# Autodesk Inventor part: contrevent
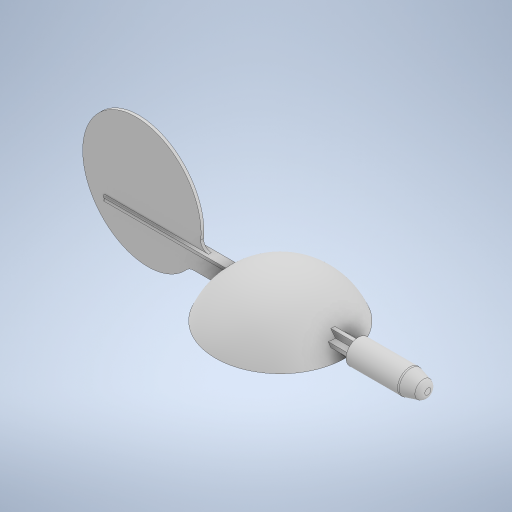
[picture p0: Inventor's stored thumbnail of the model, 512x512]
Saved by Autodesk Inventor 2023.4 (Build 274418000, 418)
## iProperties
Created: 2024-03
Part Number: contrevent
Material: Générique
Document SubType Name: Modeling
Designer: mel
Density: 1 g/cm^3
Appearance: Par défaut
Author: mel
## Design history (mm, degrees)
sketch "Esquisse1"
  geometry: L1 (0, 35.875)-(0, -35.875); A1 r 35.875 centre (0, 0) between (0, -35.875) and (0, 35.875); 1 further point
  constraints: 2 end point, 2 point on circle, 1 centre point, 1 coincident, 1 vertical
  dimensions: "d0" = 71.75 diameter of A1
revolve "Révolution1" sketch "Esquisse1" stored, may be unused: angle "d1" = 90 deg
node "Plan de construction1"
sketch "Esquisse3"
  geometry: C1 r 35.875 at (0, 0) reference; 1 further point
extrude "Extrusion1" cut sketch "Esquisse3" extent not by distance; stored distance "d3" = 0; taper "d4" = 0 deg
feature "Coque1" dims "d5" = 1.35
sketch "Esquisse4"
  geometry: C1 r 1.75 at (29.595, -0.936); C2 r 33.485 at (0, 0) reference; A1 r 2.625 centre (29.595, -0.936) between (32.034, 0.034) and (31.968, -2.058); A2 r 32.035 centre (0, 0) between (31.968, -2.058) and (32.034, 0.034) reference; 1 further point
  constraints: 4 point on circle, 2 centre point, 1 coincident
  dimensions: "d6" = 3.5 diameter of C1; "d7" = 5.25 diameter of A1; "d8" = 6.5 dimension on C2 A1
extrude "Extrusion2" join sketch "Esquisse4" stored distance "d9" = 10; taper "d10" = 0 deg
sketch "Esquisse5"
  geometry: C1 r 5 at (0, 0); C2 r 6 at (0, 0); 1 further point
  constraints: 2 centre point, 2 coincident
  dimensions: "d11" = 10 diameter of C1; "d12" = 12 diameter of C2
extrude "Extrusion3" join sketch "Esquisse5" stored distance "d13" = 10; taper "d14" = 0 deg
sketch "Esquisse6"
  geometry: C1 r 6 at (0, 0) reference; C2 r 5 at (0, 0) reference; 1 further point
extrude "Extrusion4" cut sketch "Esquisse6" distance "d15" = 3; taper "d16" = 0 deg
sketch "Esquisse7"
  geometry: L1 (0, 0)-(26.039, -26.039); L2 (0, 0)-(35.773, 0) reference; L3 (3.947, -3.947)-(16.753, -16.753); L4 (16.753, -16.753)-(16.399, -17.106); L5 (16.399, -17.106)-(3.593, -4.3); L6 (3.593, -4.3)-(3.947, -3.947); L7 (3.947, -3.947)-(16.753, -16.753); L8 (16.753, -16.753)-(17.106, -16.399); L9 (17.106, -16.399)-(4.3, -3.593); L10 (4.3, -3.593)-(3.947, -3.947); C1 r 6 at (0, 0) reference; A1 r 32.035 centre (0, 0) between (32.034, 0.034) and (31.968, -2.058) reference; 2 further points
  constraints: 20 end point, 5 parallel, 2 horizontal, 2 perpendicular, 2 point on line, 1 other
  dimensions: "d17" = 45 deg angle of L2 L1; "d18" = 0.5 distance of L3.end L4.end; "d19" = 0.5 distance of L8.end L3.end
extrude "Extrusion5" join sketch "Esquisse7" stored distance "d20" = 10; taper "d21" = 0 deg
pattern_circular "Réseau circulaire1" dims angle "d23" = 270 deg
node "Plan de construction2"
sketch "Esquisse8"
  geometry: C1 r 5 at (0, 0) reference; C2 r 5 at (0, 0); C3 r 4.25 at (0, 0); 1 further point
  constraints: 2 centre point, 2 coincident
  dimensions: "d26" = 8.5 diameter of C3
extrude "Extrusion6" join sketch "Esquisse8" stored distance "d27" = 10; taper "d28" = 0 deg
node "Plan de construction3"
sketch "Esquisse10"
  geometry: L1 (12.875, -33.485)-(12.875, 33.485) reference; L2 (23.485, 1)-(14.625, 1); L3 (14.625, 1)-(14.625, -1); L4 (14.625, -1)-(23.485, -1); L5 (23.485, -1)-(23.485, 1); L6 (20.375, 4.43)-(18.375, 4.43); L7 (18.375, 4.43)-(18.375, -4.43); L8 (18.375, -4.43)-(20.375, -4.43); L9 (20.375, -4.43)-(20.375, 4.43); 6 further points
  constraints: 16 end point, 4 parallel, 2 horizontal, 2 perpendicular, 1 midpoint
  dimensions: "d32" = 2 distance between parallel lines of L4 L2; "d33" = 1 distance from line of L2 point (12.875, 0); "d34" = 8.86 distance between parallel lines of L5 L3; "d35" = 1.75 distance between parallel lines of L3 L1; "d36" = 2 distance between parallel lines of L7 L9; "d37" = 8.86 distance between parallel lines of L8 L6 (= d34); "d38" = 4.43 distance from line of point (12.875, 0) L6 (= 0.5 x d37); "d39" = 5.5 distance between parallel lines of L7 L1
extrude "Extrusion7" join sketch "Esquisse10" stored distance "d40" = 10; taper "d41" = 0 deg
sketch "Esquisse11"
  geometry: L1 (-1, 23.485)-(-1, 20.375) reference; L2 (-1, 20.375)-(-4.43, 20.375) reference; L3 (-4.43, 20.375)-(-4.43, 18.375) reference; L4 (-4.43, 18.375)-(-1, 18.375) reference; L5 (-1, 18.375)-(-1, 14.625) reference; L6 (-1, 14.625)-(1, 14.625) reference; L7 (1, 14.625)-(1, 18.375) reference; L8 (1, 18.375)-(4.43, 18.375) reference; L9 (4.43, 18.375)-(4.43, 20.375) reference; L10 (4.43, 20.375)-(1, 20.375) reference; L11 (1, 20.375)-(1, 23.485) reference; L12 (1, 23.485)-(-1, 23.485) reference; 1 further point
extrude "Extrusion8" cut sketch "Esquisse11" distance "d42" = 23; taper "d43" = 0 deg
sketch "Esquisse12"
  geometry: L1 (-1, 18.375)-(-1, 14.625) reference; L2 (1, 20.375)-(-1, 18.375); C1 r 6.27 at (0, 19.375); 1 further point
  constraints: 2 end point, 1 centre point, 1 midpoint
  dimensions: "d44" = 12.54 diameter of C1
extrude "Extrusion9" join sketch "Esquisse12" distance "d45" = 19; taper "d46" = 0 deg
sketch "Esquisse13"
  geometry: C1 r 6.27 at (0, 0) reference; 1 further point
extrude "Extrusion10" join sketch "Esquisse13" distance "d47" = 8; taper "d48" = 0 deg
sketch "Esquisse14"
  geometry: C1 r 6.27 at (0, 0) reference; 1 further point
extrude "Extrusion11" join sketch "Esquisse14" distance "d49" = 9; taper "d50" = -15 deg
fillet "Congé1" dims "d51" = 3
node "Plan de construction4"
sketch "Esquisse16"
  geometry: L1 (12.875, -33.485)-(12.875, 33.485) reference; L2 (24.875, -2.5)-(23.375, -2.5); L3 (23.375, -2.5)-(23.375, 2.5); L4 (23.375, 2.5)-(24.875, 2.5); L5 (24.875, 2.5)-(24.875, -2.5); 2 further points
  constraints: 8 end point, 2 parallel, 1 horizontal, 1 midpoint, 1 perpendicular
  dimensions: "d53" = 5 distance between parallel lines of L4 L2; "d54" = 1.5 distance between parallel lines of L3 L5; "d55" = 2.5 distance from line of L2 point (12.875, 0) (= 0.5 x d53); "d56" = 12 distance between parallel lines of L1 L5
extrude "Extrusion12" join sketch "Esquisse16" stored distance "d57" = 9; taper "d58" = 0 deg
fillet "Congé2" dims "d59" = 1.5
node "Plan de construction5"
sketch "Esquisse17" dims "d67" = 33, "d68" = 29.5
  geometry: L1 (62.771, 0)-(62.649, 0) reference; L2 (0, 0)-(62.771, 0) reference; L3 (17.71, 10.75)-(-9.561, 52.744); 3 further points; 1 other entity
  constraints: 2 end point, 1 coincident, 1 midpoint, 2 other
  dimensions: "d64" = 45 horizontal distance of L3.start point (62.71, 0); "d65" = 10.75 distance from line of L3.start L2; "d66" = 57 deg angle of L2 L3
extrude "Extrusion13" join sketch "Esquisse17" stored distance "d69" = 1.5; taper "d70" = 0 deg
node "Plan de construction6"
sketch "Esquisse18"
  geometry: L1 (3.623, -0.75)-(67.627, -0.75) reference; L2 (67.627, 0.75)-(3.623, 0.75) reference; L3 (13.875, -0.75)-(13.875, 0.75); L4 (24.875, -2.5)-(24.875, 2.5) reference; 5 further points
  constraints: 2 end point, 2 point on line, 1 perpendicular
  dimensions: "d72" = 11 distance between parallel lines of L3 L4
extrude "Extrusion14" join sketch "Esquisse18" stored distance "d73" = 1.5; taper "d74" = 0 deg
fillet "Congé3" dims "d75" = 5
fillet "Congé4" dims "d76" = 4
node "Solide1"
node "Boucle projetée1"
node "Boucle projetée2"
node "Boucle projetée3"
other parameters: "d2" = 12.875, "d25" = -5.5, "d31" = 63.25, "d60" = -2.5
